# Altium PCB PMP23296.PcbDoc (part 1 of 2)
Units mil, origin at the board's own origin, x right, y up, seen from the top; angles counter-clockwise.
Board outline 4000 x 1600 mil, 2 copper layers (Top Layer, Bottom Layer), stack 62 mil thick; 43 components, 23 nets, 108 pads, 16 vias.
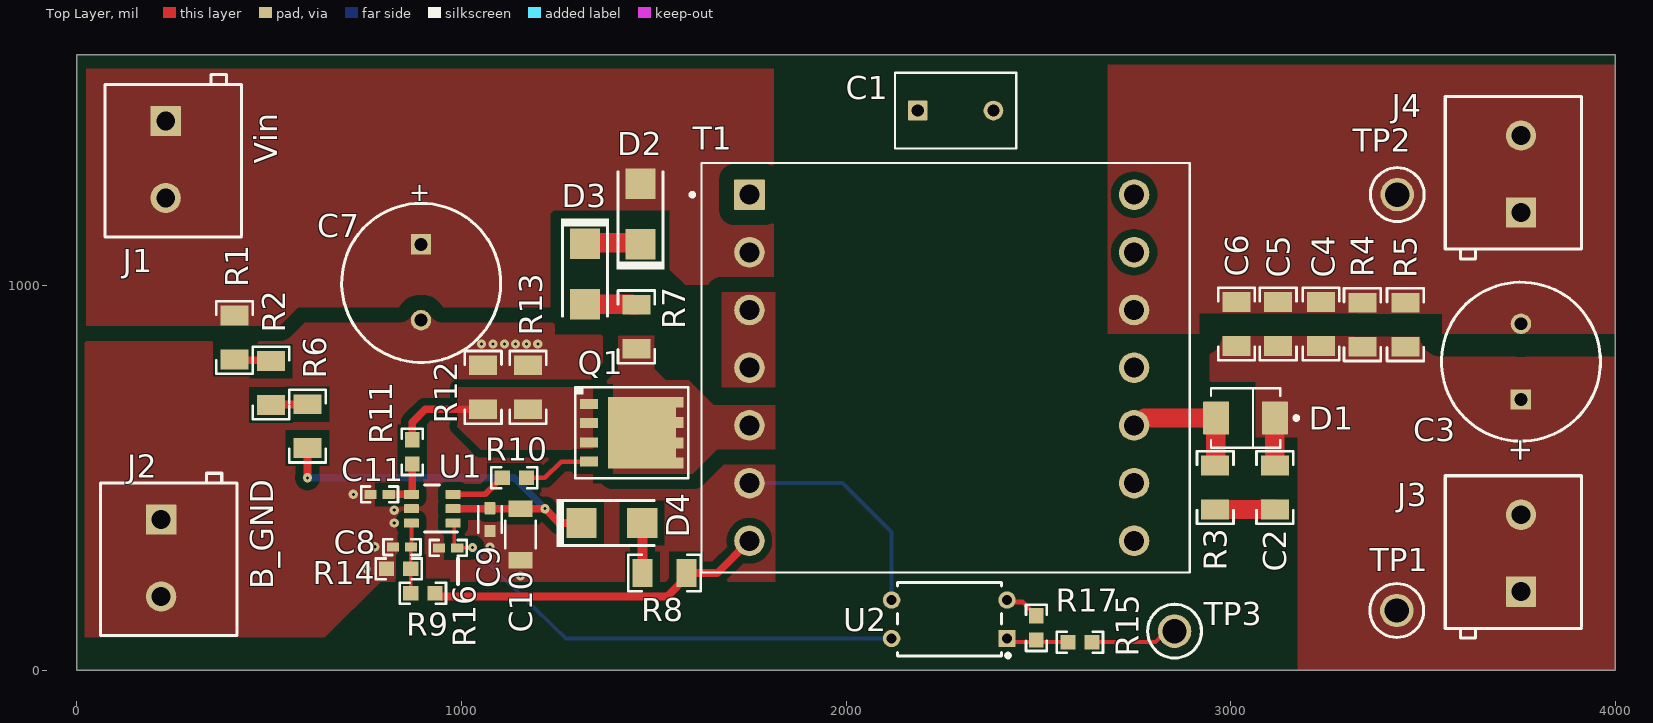
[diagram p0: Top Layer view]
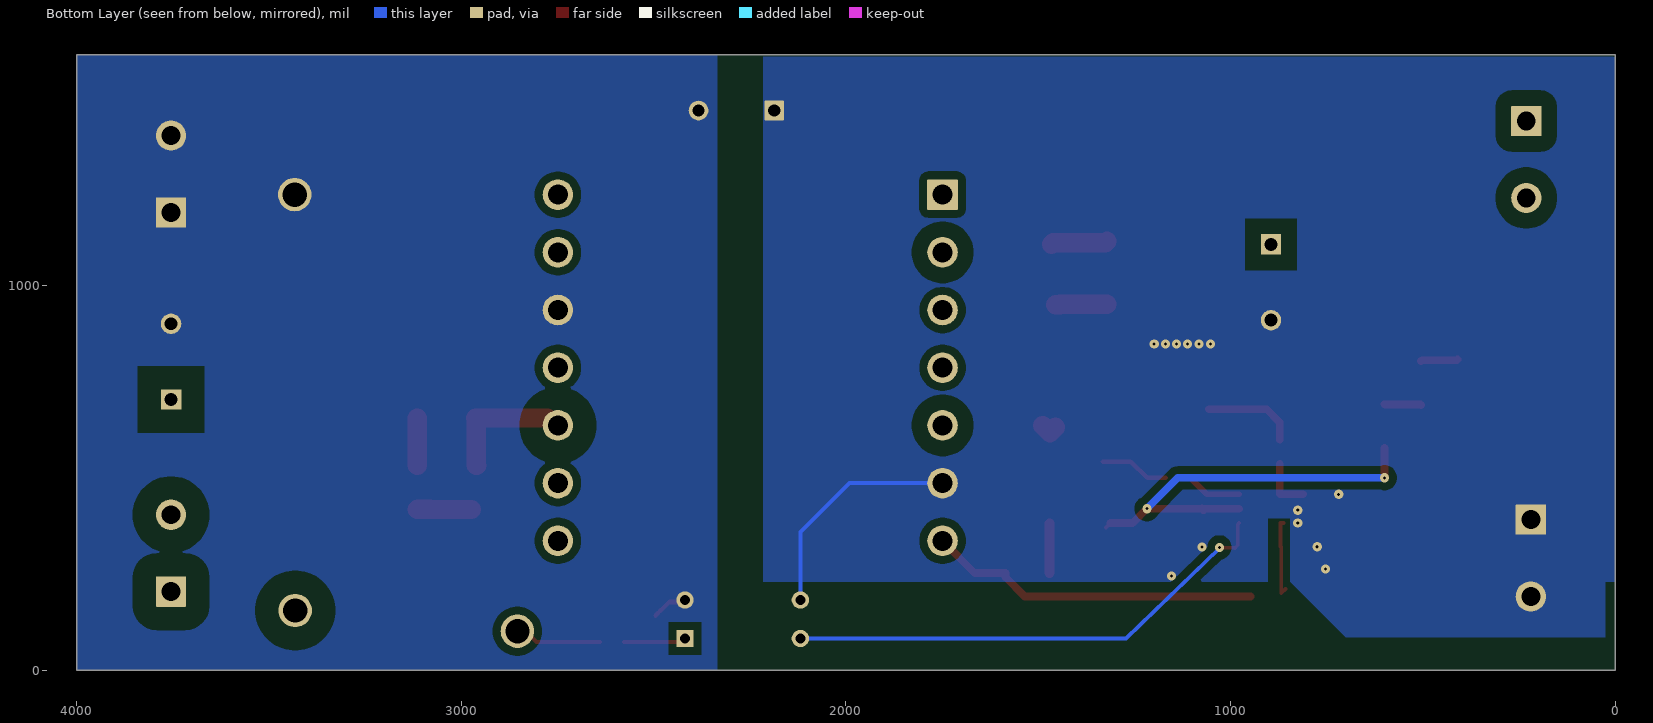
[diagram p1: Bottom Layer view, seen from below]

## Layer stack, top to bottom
Top Solder: solder mask 0.4, Solder Resist, Dk 3.5
Top Layer: signal copper 1.4
Dielectric1: core 59.2, FR-4 High Tg, Dk 4.8
Bottom Layer: signal copper 1.4
Bottom Solder: solder mask 0.4, Solder Resist, Dk 3.5

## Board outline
0,0 4000,0 4000,1600 0,1600

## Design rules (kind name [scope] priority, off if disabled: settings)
AcuteAngle [All] p1: minimum=4.50000000000000E+0001 checktracksonly=FALSE
AssemblyTestPointUsage [All] p1: valid=2
Clearance Clearance_2 [InNetClass('HV') vs Not InNetClass('HV')] p1: gap=60 ignorepadtopadclearanceinfootprint=TRUE except(0: Arc-Hole Track-Hole SMDPad-Hole THPad-Hole Via-Hole Fill-Hole Poly-Hole Region-Hole Text-Hole)
Clearance Clearance_1 [InNetClass('MV') vs Not InNetClass('MV')] p2: gap=40 ignorepadtopadclearanceinfootprint=TRUE
Clearance Clearance_Keepouts [((IsTrack Or IsArc) And Not InPoly) And IsFree and IsKeepOut vs ((IsTrack Or IsArc) And Not InPoly) And IsFree and IsKeepOut] p3: gap=0 ignorepadtopadclearanceinfootprint=TRUE
Clearance Clearance_BoardEdge_MountingHoles [OnCopper and InComponentClass('Mounting Holes') vs IsKeepOut] p4: gap=40 ignorepadtopadclearanceinfootprint=TRUE except(0: Arc-Hole Track-Hole SMDPad-Hole THPad-Hole Via-Hole Fill-Hole Poly-Hole Region-Hole Text-Hole)
Clearance Clearance_BoardEdge_Poly [OnCopper and InPoly vs IsKeepOut] p5: gap=25 ignorepadtopadclearanceinfootprint=TRUE except(0: Arc-Hole Track-Hole SMDPad-Hole THPad-Hole Via-Hole Fill-Hole Poly-Hole Region-Hole Text-Hole)
Clearance Clearance_BoardEdge [OnCopper and Not InComponentClass('Logo') and not InComponentClass('FiducialMark') and not InRegion(1000,500,4000,800) and Not IsKeepout vs IsKeepOut] p6: gap=75 ignorepadtopadclearanceinfootprint=TRUE except(0: Arc-Hole Track-Hole SMDPad-Hole THPad-Hole Via-Hole Fill-Hole Poly-Hole Region-Hole Text-Hole)
Clearance Clearance_Poly [InPolygon] p7: gap=20 ignorepadtopadclearanceinfootprint=TRUE except(0: Arc-Hole Track-Hole SMDPad-Hole THPad-Hole Via-Hole Fill-Hole Poly-Hole Region-Hole Text-Hole)
Clearance [All] p8: gap=7.87 ignorepadtopadclearanceinfootprint=TRUE except(0: Arc-SMDPad Arc-Hole Track-Hole SMDPad-Hole THPad-Hole Via-Hole Fill-Hole Poly-Hole Region-Hole Text-Hole)
ComponentClearance ComponentClearance_MountingHoles_FiducialMarks [InComponentClass('Mounting Holes') vs InComponentClass('FiducialMark')] p1: gap=20 collisioncheckmode=3 verticalgap=7 showdistances=FALSE
ComponentClearance ComponentClearance_Shunt [InComponentClass('Header') vs InComponentClass('Shunt')] p2: gap=0 collisioncheckmode=3 verticalgap=0 showdistances=FALSE
ComponentClearance ComponentClearance_Logo [InComponentClass('Logo')] p3: gap=5 collisioncheckmode=3 verticalgap=10 showdistances=FALSE
ComponentClearance ComponentClearance_ScrewToNut [(HasFootprint('KEYSTONE_4824')) vs (HasFootprint('Keystone_1903C'))] p4: gap=0 collisioncheckmode=3 verticalgap=0 showdistances=FALSE
ComponentClearance ComponentClearance_MountingHoles [InComponentClass('Mounting Holes')] p5: gap=20 collisioncheckmode=3 verticalgap=7 showdistances=FALSE
ComponentClearance ComponentClearance_SmallPassives [HasFootprint('0201*') or HasFootprint('0402*') or HasFootprint('0508') or HasFootprint('0603*') or HasFootprint('0612') or HasFootprint('0805*') or HasFootprint('0815*') or HasFootprint('0830*') or HasFootprint('1206*') or HasFootprint('1210*') or HasFootprint('1808*') or HasFootprint('1812*') or HasFootprint('1825*') or HasFootprint('2010*') or HasFootprint('2220*') or HasFootprint('2225*') or HasFootprint('2512*') or HasFootprint('2728*') or HasFootprint('3518*') vs HasFootprint('0201*') or HasFootprint('0402*') or HasFootprint('0508') or HasFootprint('0603*') or HasFootprint('0612') or HasFootprint('0805*') or HasFootprint('0815*') or HasFootprint('0830*') or HasFootprint('1206*') or HasFootprint('1210*') or HasFootprint('1808*') or HasFootprint('1812*') or HasFootprint('1825*') or HasFootprint('2010*') or HasFootprint('2220*') or HasFootprint('2225*') or HasFootprint('2512*') or HasFootprint('2728*') or HasFootprint('3518*')] p6: gap=20 collisioncheckmode=3 verticalgap=20 showdistances=FALSE
ComponentClearance ComponentClearance_THtoSMT [IsThruComponent vs IsSMTComponent] p7: gap=10 collisioncheckmode=3 verticalgap=7 showdistances=FALSE
ComponentClearance ComponentClearance_THtoTH [IsThruComponent vs IsThruComponent] p8: gap=10 collisioncheckmode=3 verticalgap=7 showdistances=FALSE
ComponentClearance [All] p9: gap=10 collisioncheckmode=3 verticalgap=7 showdistances=FALSE
DiffPairsRouting [All] p1: maxlimit=100 minlimit=10 mostfreqgap=10 toplayer_minwidth=15 toplayer_maxwidth=15 toplayer_prefwidth=15 bottomlayer_minwidth=15 bottomlayer_maxwidth=15 bottomlayer_prefwidth=15 maxuncoupledlength=1000
FabricationTestPointUsage TestPointUsage [All] p1: valid=2 allowmultiple=FALSE
FabricationTestpoint Testpoint [All] p1: side=3 testpointundercomponent=TRUE minsize=40 maxsize=100 preferedsize=60 minholesize=0 maxholesize=40 preferedholesize=32 testpointgrid=1 allowsidetop=TRUE allowsidebottom=TRUE usegrid=TRUE gridtolerance=0.01
FanoutControl Fanout_LCC [IsLCC] p1: bgadir=Out bgaviamode=Centered fanoutstyle=Auto fanoutdirection=Alternating viagrid=1 // Fanout_LCC (Default Rule)
FanoutControl Fanout_BGA [IsBGA] p2: bgadir=Out bgaviamode=Centered fanoutstyle=Auto fanoutdirection=Alternating viagrid=1 // Fanout_BGA (Default Rule)
FanoutControl Fanout_Default [All] p4: bgadir=Out bgaviamode=Centered fanoutstyle=Auto fanoutdirection=Alternating viagrid=1 // Fanout_Default (Default Rule)
FanoutControl Fanout_Small [(CompPinCount < 5)] p5: bgadir=Out bgaviamode=Centered fanoutstyle=Auto fanoutdirection=OutThenIn viagrid=1 // Fanout_Small (Default Rule)
Height [All] p1: minheight=0 maxheight=3000 prefheight=500
HoleSize [All] p1: absolutevalues=TRUE maxlimit=501 minlimit=7 maxpercent=80.000 minpercent=20.000
MinimumAnnularRing MinimumAnnularRing_ThermalPadVias [IsVia and InAnyComponent] p1: minimumring=5.91
MinimumAnnularRing [All] p2: minimumring=5
MinimumSolderMaskSliver MinimumSolderMaskSliver_Logo [InComponentClass('Logo') vs InComponentClass('Logo')] p1: minsoldermaskwidth=0.7
MinimumSolderMaskSliver [All] p2: minsoldermaskwidth=3
PlaneConnect [All] p1: planeconnectstyle=Direct reliefexpansion=10 reliefentries=4 reliefconductorwidth=10 reliefairgap=10
PolygonConnect PolygonConnect_16 [All vs IsNamedPolygon('C106_2') Or  IsNamedPolygon('Vout') Or  IsNamedPolygon('IN+') Or  IsNamedPolygon('Q203_5') Or  IsNamedPolygon('IN+') Or  IsNamedPolygon('Q201_5') Or  IsNamedPolygon('C108_2') Or  IsNamedPolygon('SGND') Or  IsNamedPolygon('IN+') Or  IsNamedPolygon('SGND') Or  IsNamedPolygon('Q203_5') Or  IsNamedPolygon('IN+') Or  IsNamedPolygon('SGND') Or  IsNamedPolygon('GND') Or  IsNamedPolygon('C113_2') Or  IsNamedPolygon('C107_2') Or  IsNamedPolygon('C107_2') Or  IsNamedPolygon('Vout') Or  IsNamedPolygon('SIGNAL_LAYER_1_GND_P074') Or  IsNamedPolygon('HV') Or  IsNamedPolygon('C108_2') Or  IsNamedPolygon('C103_2') Or  IsNamedPolygon('Q201_5') Or  IsNamedPolygon('Vout') Or  IsNamedPolygon('C109_2') Or  IsNamedPolygon('Q201_5') Or  IsNamedPolygon('GND') Or  IsNamedPolygon('C107_2') Or  IsNamedPolygon('C102_1') Or  IsNamedPolygon('GND') Or  IsNamedPolygon('SGND') Or  IsNamedPolygon('HS') Or  IsNamedPolygon('Q203_5') Or  IsNamedPolygon('Q201_5') Or  IsNamedPolygon('Q203_5')] p1: connectstyle=Direct reliefconductorwidth=10 reliefentries=4 polygonreliefangle="90 Angle" airgapwidth=10
PolygonConnect PolygonConnect_15 [All vs IsNamedPolygon('C109_2') Or  IsNamedPolygon('C107_2') Or  IsNamedPolygon('HV') Or  IsNamedPolygon('Q203_5') Or  IsNamedPolygon('C107_2') Or  IsNamedPolygon('HS') Or  IsNamedPolygon('Q201_5') Or  IsNamedPolygon('Q203_5') Or  IsNamedPolygon('C106_2') Or  IsNamedPolygon('C108_2') Or  IsNamedPolygon('Vout') Or  IsNamedPolygon('Q203_5') Or  IsNamedPolygon('C108_2') Or  IsNamedPolygon('C113_2') Or  IsNamedPolygon('Q203_5') Or  IsNamedPolygon('Q201_5') Or  IsNamedPolygon('C107_2') Or  IsNamedPolygon('C102_1') Or  IsNamedPolygon('SGND') Or  IsNamedPolygon('GND') Or  IsNamedPolygon('SGND') Or  IsNamedPolygon('GND') Or  IsNamedPolygon('IN+') Or  IsNamedPolygon('IN+') Or  IsNamedPolygon('Q201_5') Or  IsNamedPolygon('Q201_5') Or  IsNamedPolygon('SGND') Or  IsNamedPolygon('SGND') Or  IsNamedPolygon('Vout') Or  IsNamedPolygon('Vout') Or  IsNamedPolygon('IN+') Or  IsNamedPolygon('GND') Or  IsNamedPolygon('IN+') Or  IsNamedPolygon('GND')] p2: connectstyle=Direct reliefconductorwidth=10 reliefentries=4 polygonreliefangle="90 Angle" airgapwidth=10
PolygonConnect PolygonConnect_14 [All vs IsNamedPolygon('C106_2') Or  IsNamedPolygon('C107_2') Or  IsNamedPolygon('C107_2') Or  IsNamedPolygon('C107_2') Or  IsNamedPolygon('C102_1') Or  IsNamedPolygon('Q203_5') Or  IsNamedPolygon('Vout') Or  IsNamedPolygon('Q203_5') Or  IsNamedPolygon('Q203_5') Or  IsNamedPolygon('Q201_5') Or  IsNamedPolygon('C108_2') Or  IsNamedPolygon('Q203_5') Or  IsNamedPolygon('HS') Or  IsNamedPolygon('HV') Or  IsNamedPolygon('C108_2') Or  IsNamedPolygon('Q201_5') Or  IsNamedPolygon('C109_2') Or  IsNamedPolygon('Q201_5') Or  IsNamedPolygon('Q201_5') Or  IsNamedPolygon('C113_2')] p3: connectstyle=Direct reliefconductorwidth=10 reliefentries=4 polygonreliefangle="90 Angle" airgapwidth=10
PolygonConnect PolygonConnect_13 [All vs IsNamedPolygon('C102_1') Or  IsNamedPolygon('HV') Or  IsNamedPolygon('C107_2') Or  IsNamedPolygon('C109_2') Or  IsNamedPolygon('C107_2') Or  IsNamedPolygon('C108_2') Or  IsNamedPolygon('C106_2') Or  IsNamedPolygon('C108_2') Or  IsNamedPolygon('C113_2') Or  IsNamedPolygon('C107_2')] p4: connectstyle=Direct reliefconductorwidth=10 reliefentries=4 polygonreliefangle="90 Angle" airgapwidth=10
PolygonConnect PolygonConnect_12 [All vs IsNamedPolygon('C107_2') Or  IsNamedPolygon('C113_2') Or  IsNamedPolygon('C106_2') Or  IsNamedPolygon('C107_2') Or  IsNamedPolygon('C107_2') Or  IsNamedPolygon('C102_1')] p5: connectstyle=Direct reliefconductorwidth=10 reliefentries=4 polygonreliefangle="90 Angle" airgapwidth=10
PolygonConnect PolygonConnect_11 [All vs IsNamedPolygon('C106_2') Or  IsNamedPolygon('C102_1') Or  IsNamedPolygon('C107_2') Or  IsNamedPolygon('C107_2') Or  IsNamedPolygon('C107_2')] p6: connectstyle=Direct reliefconductorwidth=10 reliefentries=4 polygonreliefangle="90 Angle" airgapwidth=10
PolygonConnect PolygonConnect_10 [All vs IsNamedPolygon('C106_2')] p7: connectstyle=Direct reliefconductorwidth=10 reliefentries=4 polygonreliefangle="90 Angle" airgapwidth=10
PolygonConnect PolygonConnect_9 [All vs IsNamedPolygon('C11_1') Or  IsNamedPolygon('Vin') Or  IsNamedPolygon('Vin') Or  IsNamedPolygon('5V') Or  IsNamedPolygon('D6_2') Or  IsNamedPolygon('Q3_3') Or  IsNamedPolygon('GND2') Or  IsNamedPolygon('GND2') Or  IsNamedPolygon('GND') Or  IsNamedPolygon('Q3_4') Or  IsNamedPolygon('12V5') Or  IsNamedPolygon('GND') Or  IsNamedPolygon('12V5') Or  IsNamedPolygon('D3_1')] p8: connectstyle=Direct reliefconductorwidth=10 reliefentries=4 polygonreliefangle="90 Angle" airgapwidth=10
PolygonConnect PolygonConnect_8 [All vs IsNamedPolygon('C11_1') Or  IsNamedPolygon('Vin') Or  IsNamedPolygon('12V5') Or  IsNamedPolygon('Q3_3') Or  IsNamedPolygon('GND2') Or  IsNamedPolygon('GND2') Or  IsNamedPolygon('5V') Or  IsNamedPolygon('Q3_4') Or  IsNamedPolygon('12V5')] p9: connectstyle=Direct reliefconductorwidth=10 reliefentries=4 polygonreliefangle="90 Angle" airgapwidth=10
PolygonConnect PolygonConnect_7 [All vs IsNamedPolygon('GND2') Or  IsNamedPolygon('GND2') Or  IsNamedPolygon('5V') Or  IsNamedPolygon('12V5') Or  IsNamedPolygon('12V5') Or  IsNamedPolygon('C11_1')] p10: connectstyle=Direct reliefconductorwidth=10 reliefentries=4 polygonreliefangle="90 Angle" airgapwidth=10
PolygonConnect PolygonConnect_6 [All vs IsNamedPolygon('GND2') Or  IsNamedPolygon('SGND') Or  IsNamedPolygon('GND1') Or  IsNamedPolygon('C901_1') Or  IsNamedPolygon('SGND') Or  IsNamedPolygon('GND2') Or  IsNamedPolygon('GND1')] p11: connectstyle=Direct reliefconductorwidth=10 reliefentries=4 polygonreliefangle="90 Angle" airgapwidth=10
PolygonConnect PolygonConnect_5 [All vs IsNamedPolygon('GND1') Or  IsNamedPolygon('GND1')] p12: connectstyle=Direct reliefconductorwidth=10 reliefentries=4 polygonreliefangle="90 Angle" airgapwidth=10
PolygonConnect PolygonConnect_4 [All vs IsNamedPolygon('C21_1') Or  IsNamedPolygon('C5_1') Or  IsNamedPolygon('C12_2') Or  IsNamedPolygon('C2_2') Or  IsNamedPolygon('C13_1') Or  IsNamedPolygon('C28_1') Or  IsNamedPolygon('C6_1') Or  IsNamedPolygon('GND') Or  IsNamedPolygon('GND2') Or  IsNamedPolygon('C14_1') Or  IsNamedPolygon('C13_1') Or  IsNamedPolygon('Q1_3') Or  IsNamedPolygon('C14_1') Or  IsNamedPolygon('C5_1') Or  IsNamedPolygon('GND2') Or  IsNamedPolygon('C28_1') Or  IsNamedPolygon('D5_2') Or  IsNamedPolygon('D6_2') Or  IsNamedPolygon('D2_1') Or  IsNamedPolygon('C12_2') Or  IsNamedPolygon('D2_1') Or  IsNamedPolygon('C4_1') Or  IsNamedPolygon('C4_1') Or  IsNamedPolygon('C2_2') Or  IsNamedPolygon('GND') Or  IsNamedPolygon('C33_1') Or  IsNamedPolygon('C9_1')] p13: connectstyle=Direct reliefconductorwidth=10 reliefentries=4 polygonreliefangle="90 Angle" airgapwidth=10
PolygonConnect PolygonConnect_3 [All vs IsNamedPolygon('C28_1') Or  IsNamedPolygon('C12_2') Or  IsNamedPolygon('C28_1') Or  IsNamedPolygon('C9_1') Or  IsNamedPolygon('D5_2') Or  IsNamedPolygon('C12_2') Or  IsNamedPolygon('C2_2') Or  IsNamedPolygon('C14_1') Or  IsNamedPolygon('C4_1') Or  IsNamedPolygon('C14_1') Or  IsNamedPolygon('D6_2') Or  IsNamedPolygon('GND2') Or  IsNamedPolygon('Q1_3') Or  IsNamedPolygon('C5_1') Or  IsNamedPolygon('D2_1') Or  IsNamedPolygon('C4_1') Or  IsNamedPolygon('C13_1') Or  IsNamedPolygon('C5_1') Or  IsNamedPolygon('C13_1') Or  IsNamedPolygon('C33_1') Or  IsNamedPolygon('D2_1') Or  IsNamedPolygon('GND') Or  IsNamedPolygon('GND') Or  IsNamedPolygon('GND2') Or  IsNamedPolygon('C2_2') Or  IsNamedPolygon('C6_1') Or  IsNamedPolygon('C21_1')] p14: connectstyle=Direct reliefconductorwidth=10 reliefentries=4 polygonreliefangle="90 Angle" airgapwidth=10
PolygonConnect PolygonConnect_2 [All vs IsNamedPolygon('C21_1') Or  IsNamedPolygon('C4_1') Or  IsNamedPolygon('D5_2') Or  IsNamedPolygon('C5_1') Or  IsNamedPolygon('C14_1') Or  IsNamedPolygon('C13_1') Or  IsNamedPolygon('C4_1') Or  IsNamedPolygon('C33_1') Or  IsNamedPolygon('C12_2') Or  IsNamedPolygon('D2_1') Or  IsNamedPolygon('C2_2') Or  IsNamedPolygon('C28_1') Or  IsNamedPolygon('C12_2') Or  IsNamedPolygon('D2_1') Or  IsNamedPolygon('C5_1') Or  IsNamedPolygon('Q1_3') Or  IsNamedPolygon('GND') Or  IsNamedPolygon('D6_2') Or  IsNamedPolygon('C6_1') Or  IsNamedPolygon('C2_2') Or  IsNamedPolygon('C14_1') Or  IsNamedPolygon('C28_1') Or  IsNamedPolygon('C13_1') Or  IsNamedPolygon('C9_1') Or  IsNamedPolygon('GND')] p15: connectstyle=Direct reliefconductorwidth=10 reliefentries=4 polygonreliefangle="90 Angle" airgapwidth=10
PolygonConnect PolygonConnect_1 [All vs IsNamedPolygon('C28_1') Or  IsNamedPolygon('D5_2') Or  IsNamedPolygon('C5_1') Or  IsNamedPolygon('C5_1') Or  IsNamedPolygon('D2_1') Or  IsNamedPolygon('C21_1') Or  IsNamedPolygon('C9_1') Or  IsNamedPolygon('C4_1') Or  IsNamedPolygon('C14_1') Or  IsNamedPolygon('C28_1') Or  IsNamedPolygon('C6_1') Or  IsNamedPolygon('C12_2') Or  IsNamedPolygon('C33_1') Or  IsNamedPolygon('C4_1') Or  IsNamedPolygon('C13_1') Or  IsNamedPolygon('C12_2') Or  IsNamedPolygon('D6_2') Or  IsNamedPolygon('C2_2') Or  IsNamedPolygon('C14_1') Or  IsNamedPolygon('D2_1') Or  IsNamedPolygon('C2_2') Or  IsNamedPolygon('C13_1')] p16: connectstyle=Direct reliefconductorwidth=10 reliefentries=4 polygonreliefangle="90 Angle" airgapwidth=10
PolygonConnect [All] p17: connectstyle=Direct reliefconductorwidth=10 reliefentries=4 polygonreliefangle="90 Angle" airgapwidth=10
RoutingVias ThermalPadVias [IsVia and not InNet('SGND')and not InNet('Vout')] p1: holewidth=7.87 width=19.68 viastyle="Through Hole" minholewidth=7.87 minwidth=19.68 maxholewidth=17 maxwidth=35
RoutingVias [IsVia and not InNet('SGND')and not InNet('Vout')] p2: holewidth=16 width=34 viastyle="Through Hole" minholewidth=7.87 minwidth=20 maxholewidth=40 maxwidth=65
SilkToBoardRegionClearance [Not ((IsComment or IsDesignator) And (Hide <> 'False')) and not InRegion(1000,500,4000,800)] p1:
SilkToSilkClearance SilkToSilkClearance_Pb-FreeLogo [(HasFootprint('Pb-Free_Overlay_Medium') OR HasFootprint('Pb-Free_Overlay_Small')) vs (HasFootprint('Pb-Free_Overlay_Medium') OR HasFootprint('Pb-Free_Overlay_Small'))] p1: silktosilkclearance=0
SilkToSilkClearance [All] p2: silktosilkclearance=3
SilkToSolderMaskClearance "Silk to Solder Mask Opening" [All] p1: minsilkscreentomaskgap=1 clearancetoexposedcopper=FALSE
SolderMaskExpansion [All] p1: expansion=1.97 istentingtop=FALSE
UnpouredPolygon [All] p1: allowunpoured=TRUE allowshelved=TRUE
Width [All] p1: maxlimit=100 minlimit=6 preferedwidth=10 checkconnectedcopper=TRUE
13 further rules are at their usual default settings.

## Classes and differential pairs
net class MV: NetC7_1 NetD2_1 NetD3_2 NetQ1_5
net class HV: NetC2_1 NetC2_2 NetD1_2

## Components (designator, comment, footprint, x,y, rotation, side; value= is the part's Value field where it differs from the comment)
C1 "DE2E3KY222MN2AM01F" FP-DE2E3KY222MN2AM01F_RADIAL-MFG 2285,1455 r0 top value=2.2nF
C2 "GRM31A5C2J101JW01D" 1206 3115.03,475 r270 top value=100pF
C3 "UCA2D220MPD1TD" CA_1000x2000 3754.92,802.1 r90 top value=22uF
C4 "C1206C104K2RACTU" 1206 3235,900 r90 top value=0.1uF
C5 "C1206C104K2RACTU" 1206 3123.57,900 r90 top value=0.1uF
C6 "C1206C104K2RACTU" 1206 3015.3,900 r90 top value=0.1uF
C7 "UPW2D220MPD1TD" UPW_1000x2000 895,1008.43 r270 top value=22uF
C8 "C0402C100C8GACTU" 0402 845.54,320 r180 top value=10pF
C9 "06035C104J4Z2A" FP-06035C104J4Z2A_0603-MFG 1074.33,391.47 r90 top value=100nF
C10 "C3216X5R1H225K160AB" 1206_180 1153.72,352.84 r270 top value=2.2uF
C11 "C0402C100C8GACTU" 0402 787.4,457.17 r180 top value=10pF
D1 "MURS260-E3/5BT" FP-MURS260-E3/5BT_SMB-MFG 3038.76,655.56 r180 top
D2 "SMAJ120A" SMA 1465.55,1186.24 r90 top value=120V
D3 "US1M-13-F" SMA 1321.48,1030 r270 top value=1000V
D4 "NRVTSA4100ET3G" SMA 1391.19,382.37 r0 top value=100V
J1 "ED120/2DS" On-Shore_ED120_2DS 231.3,1327.69 r270 top
J2 "ED120/2DS" On-Shore_ED120_2DS 219.49,291.47 r270 top
J3 "ED120/2DS" On-Shore_ED120_2DS 3754.92,304.07 r90 top
J4 "ED120/2DS" On-Shore_ED120_2DS 3754.92,1289.89 r90 top
Q1 "BSC13DN30NSFD" PG-TDSON-8 1442.91,617.29 r0 top value=300V
R1 "RC1206FR-07470KL" 1206 410,865 r90 top value=470k
R2 "RC1206FR-07470KL" 1206 505,746.53 r90 top value=470k
R3 "ERJ-8GEY0R00V" 1206 2960,475 r270 top value=0
R4 "RC1206FR-07100KL" 1206 3342.46,898.17 r270 top value=100k
R5 "RC1206FR-07100KL" 1206 3454.15,898.17 r270 top value=100k
R6 "RC1206FR-07470KL" 1206 600,634.62 r90 top value=470k
R7 "CRCW120615R0JNEA" 1206 1455.03,892.65 r90 top value=15
R8 "RC1206FR-074R7L" 1206 1528.05,252.42 r0 top value=4.70
R9 "RT0603BRD0787K6L" 0603 899.82,200 r0 top value=87.6k
R10 "ERJ-3GEY0R00V" 0603 1137.66,500.13 r0 top value=0
R11 "CRCW06031K24FKEA" 0603 872.04,567.62 r90 top value=1.24k
R12 "ERJ-8RQFR47V" 1206 1056.41,735.4 r270 top value=0.47
R13 "ERJ-8RQFR47V" 1206 1173.09,735.4 r270 top value=0.47
R14 "CRCW060328K7FKEA" 0603 837.04,263.25 r0 top value=28.7k
R15 "M55342K12B10E0T" 0603 2608.27,72.75 r0 top value=10.0k
R16 "RC0402FR-07100KL" 0402 965.76,317.78 r0 top value=100k
R17 "M55342K12B10E0T" 0603 2495,110 r270 top value=10.0k
T1 "750320243" FP-750320243_PTH14_32MM25_27MM05-MFG 2258.86,786.35 r0 top
TP1 "5010" Keystone5010 3432.02,155.13 r0 top
TP2 "5011" Keystone5011 3433.28,1236.35 r0 top
TP3 "5013" Keystone5013 2854.33,101.3 r0 top
U1 "UCC28704DBVR-1" DBV0006A_N 924.21,419.77 r180 top
U2 "VO618A-3" DIP-4 2268.7,132.34 r180 top

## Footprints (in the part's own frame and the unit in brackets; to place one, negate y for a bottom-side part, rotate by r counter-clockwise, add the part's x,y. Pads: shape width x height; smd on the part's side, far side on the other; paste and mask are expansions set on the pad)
0402 [mm] "0402 from SM-752 data"
  rect 0.8x0.6 smd: 1(-0.6,0) 2(0.6,0)
  silkscreen extent -1.22,-0.52 1.22,0.52, body extent -0.55,-0.3 0.55,0.3, height 0.6
0603 [mm] "0603 from SM-752 data"
  rect 1x0.95 smd: 1(-0.8,0) 2(0.8,0)
  silkscreen extent -1.52,-0.69 1.52,0.69, body extent -0.87,-0.47 0.87,0.47, height 1
1206 [mm] "1206 from SM-752 data"
  rect 1.3x1.85 smd: 1(-1.45,0) 2(1.45,0)
  silkscreen extent -2.4,-1.21 2.4,1.21, body extent -1.7,-0.9 1.7,0.9, height 1.35
1206_180 [mm] "1206_180"
  rect 1.1x1.6 smd: 1(-1.7,0) 2(1.7,0)
  silkscreen extent -0.9,-1 0.9,1, body extent -1.75,-0.95 1.75,0.95, height 1.8
CA_1000x2000 [mm] "TH, 2-Leads, Dia 10mm, Lead Spacing 5mm"
  rect 1.35x1.35 hole 0.85: 1(-2.5,0)
  round 1.35 hole 0.85: 2(2.5,0)
  silkscreen extent -5.25,-5.25 5.25,5.25, body extent -5.21,-5.24 5.24,5.24, height 21.51
DBV0006A_N [mm] "SOT23, 6-Leads, Body 2.9x1.6mm, Pitch 0.95mm, Lead Span 2.8mm, IPC Medium Density"
  rrect17% 1x0.6 smd: 1(-1.375,0.95) 2(-1.375,0) 3(-1.375,-0.95) 4(1.375,-0.95) 5(1.375,0) 6(1.375,0.95)
  silkscreen extent -1.68,-1.55 0.5,1.55, body extent -1.42,-1.46 1.42,1.46, height 1.12
DIP-4 [mm] "DIP, 4-Leads, Body 6.86x4.83mm, Pitch 2.54mm"
  rect 1.15x1.15 hole 0.65: 1(-3.81,1.27)
  round 1.15 hole 0.65: 2(-3.81,-1.27) 3(3.81,-1.27) 4(3.81,1.27)
  silkscreen extent -4,-2.41 3.43,2.52, body extent -4.02,-2.41 4.02,2.41, height 5.59
FP-06035C104J4Z2A_0603-MFG [mm]
  rrect13% 0.8x0.75 smd paste+0 mask+0: 1(-0.75,0) 2(0.75,0)
  silkscreen extent -0.87,-0.77 0.87,0.77, body extent -1.25,-0.58 1.25,0.58, height 0.25
FP-750320243_PTH14_32MM25_27MM05-MFG [mm]
  rrect5% 2.02x2.02 hole 1.32 paste-1000 mask+0: 1(-12.95,11.43)
  round 2.02 hole 1.32 paste-1000 mask+0: 2(-12.95,7.62) 3(-12.95,3.81) 4(-12.95,0) 5(-12.95,-3.81) 6(-12.95,-7.62) 7(-12.95,-11.43) 8(12.45,-11.43) 9(12.45,-7.62) 10(12.45,-3.81) 11(12.45,0) 12(12.45,3.81) 13(12.45,7.62) 14(12.45,11.43)
  silkscreen extent -16.85,-13.52 16.12,13.52, body extent -16.22,-13.62 16.22,13.62, height 0.25
FP-DE2E3KY222MN2AM01F_RADIAL-MFG [mm]
  rrect8% 1.3x1.3 hole 0.8 paste-1000 mask+0: 1(-2.5,0)
  round 1.3 hole 0.8 paste-1000 mask+0: 2(2.5,0)
  silkscreen extent -4,-2.5 4,2.5, body extent -4.1,-2.6 4.1,2.6, height 0.25
FP-MURS260-E3/5BT_SMB-MFG [mm]
  rrect6% 1.716x2.18 smd paste+0 mask+0: 1(-1.937,0) 2(1.937,0)
  silkscreen extent -3.47,-1.97 2.28,1.97, body extent -2.9,-2.07 2.89,2.07, height 0.25
Keystone5010 [mil] "Keystone Multipurpose loops"
  round 87 hole 63: 1(0,0)
  silkscreen extent -70,-70 70,70, body extent -63,-63 63,62, height 319
Keystone5011 [mil] "Keystone Multipurpose loops"
  round 87 hole 63: 1(0,0)
  silkscreen extent -70,-70 70,70, body extent -63,-63 63,62, height 319
Keystone5013 [mil] "Keystone Multipurpose loops"
  round 87 hole 63: 1(0,0)
  silkscreen extent -70,-70 70,70, body extent -63,-63 63,62, height 319
On-Shore_ED120_2DS [mm] "ONSHORE"
  rrect5% 2x2 hole 1.25: 1(-2.54,0)
  round 2 hole 1.25: 2(2.54,0)
  silkscreen extent -5.6,-4 5.12,5, body extent -5.78,-4 5.08,5, height 13
PG-TDSON-8 [mm] "Infineon recommended land pattern"
  rect 1.2x0.65 smd: 1(-2.825,1.905) 2(-2.825,0.635) 3(-2.825,-0.635) 4(-2.825,-1.905)
  rect 0.5x0.7 smd: 5(3.175,-2) 6(3.175,-0.675) 7(3.175,0.675) 8(3.175,2)
  rect 4.5x4.7 smd paste-2.25: 9(0.675,0)
  silkscreen extent -3.74,-3 3.74,3, body extent -3.17,-2.89 3.17,2.9, height 1.1
SMA [mm] "Molded Diode, 2-Leads, Body 4.3x2.6mm, IPC Medium Density, based on OnSemi component dimensions and land pattern"
  rect 2x2 smd: 1(-2,0) 2(2,0)
  silkscreen extent -3.66,-1.57 2.79,1.57, body extent -2.6,-1.3 2.6,1.3, height 2.42
UPW_1000x2000 [mm] "TH, 2-Leads, Dia 10mm, Lead Spacing 5mm"
  rect 1.35x1.35 hole 0.85: 1(-2.5,0)
  round 1.35 hole 0.85: 2(2.5,0)
  silkscreen extent -5.22,-5.24 5.29,5.26, body extent -5.25,-5.25 5.26,5.25, height 22.01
